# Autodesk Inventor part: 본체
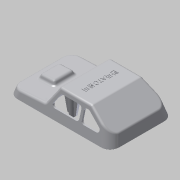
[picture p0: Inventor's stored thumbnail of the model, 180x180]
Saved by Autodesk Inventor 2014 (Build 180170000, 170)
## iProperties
Created: 2015-05
Part Number: 본체
Material: ABS 플라스틱
Document SubType Name: Modeling
Designer: Administrator
Density: 1.06 g/cm^3
Appearance: 매끄러움 - 흰색
Mass: 32.5107 g
Surface Area: 310.046 cm^2
Volume: 30.6705 cm^3
Author: Administrator
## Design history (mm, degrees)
sketch "스케치2"
  geometry: L1 (61, 0)-(-61, 0); L2 (-61, 0)-(-61, 10); L3 (-61, 10)-(-57.782, 12.011); L4 (6.614, 30)-(19.058, 10.086); L5 (19.058, 10.086)-(58.856, 8); L6 (61, 7.888)-(61, 0); L7 (61, 0)-(58.856, 8); L8 (58.856, 8)-(61, 7.888); L9 (-61, 0)-(-57.782, 12.011); L10 (6.614, 30)-(-31, 30); L11 (-31, 30)-(-57.782, 12.011); 2 further points
  constraints: 22 end point, 3 perpendicular, 1 coincident, 1 collinear, 1 horizontal, 1 midpoint, 1 parallel
  dimensions: "d0" = 122 distance of L1.start L1.end; "d1" = 3 deg angle of L1 L5; "d2" = 15 deg angle of L6 L7; "d3" = 8 vertical distance of L1.start L5.end; "d4" = 42 distance of L4.end L6.start; "d5" = 125 deg angle of L5 L4; "d6" = 15 deg angle of L2 L9; "d7" = 30 horizontal distance of L10.end L1.end; "d8" = 20 vertical distance of L10.end L2.end; "d39" = 30 horizontal distance of L2.end L10.end
extrude "돌출1" new body sketch "스케치2" stored distance "d10" = 76; taper "d11" = 0 deg
sketch "스케치3"
  geometry: L1 (-38, 30)-(-38, 10.086) reference; L2 (38, 30)-(-38, 30) reference; L3 (-38, 30)-(-29.962, 30); L4 (-29.962, 30)-(-38, 0); L5 (-38, 0)-(-38, 30); 2 further points
  constraints: 6 end point, 2 collinear, 1 coincident, 1 perpendicular
  dimensions: "d12" = 15 deg angle of L1 L4
extrude "돌출2" cut sketch "스케치3" stored distance "d13" = 76; taper "d14" = 0 deg
fillet "모깎기1" dims "d15" = 12
sketch "스케치4"
  geometry: L1 (-39.853, 59.563)-(-39.853, 11.032) reference; L2 (-31.413, 48.298)-(-11.413, 48.298); L3 (-11.413, 48.298)-(-11.413, 22.298); L4 (-11.413, 22.298)-(-31.413, 22.298); L5 (-31.413, 22.298)-(-31.413, 48.298); L6 (-42.413, 8.889)-(-42.413, 61.706) reference; 3 further points
  constraints: 8 end point, 2 midpoint, 2 parallel, 1 horizontal, 1 horizontal alignment, 1 perpendicular
  dimensions: "d16" = 20 distance of L2.start L2.end; "d17" = 26 distance of L2.end L3.end; "d18" = 11 distance between parallel lines of L6 L5
extrude "돌출3" join sketch "스케치4" distance "d19" = 5; taper "d20" = -20 deg
fillet "모깎기2" dims "d21" = 3
fillet "모깎기3" dims "d22" = 3
feature "쉘1" dims "d23" = 2
sketch "스케치5"
  geometry: L1 (98.679, -73.929)-(0.139, -73.929) reference; L2 (-9.521, -64.27)-(-9.521, -11.73) reference; L3 (0.139, -2.071)-(98.679, -2.071) reference; L4 (108.338, -11.73)-(108.338, -64.27) reference; L5 (98.679, -1.071)-(0.139, -1.071); L6 (-10.521, -11.73)-(-10.521, -64.27); L7 (0.139, -74.929)-(98.679, -74.929); L8 (109.338, -64.27)-(109.338, -11.73); 5 further points; 4 other entities
  constraints: 8 end point, 7 parallel, 16 other
  dimensions: "d24" = 1 distance between parallel lines of L5 L3
extrude "돌출4" join sketch "스케치5" distance "d25" = 1; taper "d26" = 0 deg
node "작업 평면2"
sketch "스케치7"
  geometry: L1 (7.495, 28.59)-(18.23, 11.41) reference; L2 (-30.086, 30)-(4.951, 30) reference; L3 (-46.246, 19.759)-(-31.759, 29.49) reference; L4 (10.347, 14.59)-(4.723, 23.59); L5 (2.179, 25)-(-17.785, 25); L6 (-20.785, 22)-(-20.785, 13); L7 (-17.785, 10)-(7.803, 10); L8 (-23.808, 22)-(-23.808, 13); L9 (-26.808, 10)-(-41.962, 10); L10 (-43.634, 15.49)-(-30.235, 24.49); L11 (-28.563, 25)-(-26.808, 25); A1 r 3 centre (2.179, 22) between (4.723, 23.59) and (2.179, 25); A2 r 3 centre (7.803, 13) between (7.803, 10) and (10.347, 14.59); A3 r 3 centre (-17.785, 13) between (-20.785, 13) and (-17.785, 10); A4 r 3 centre (-17.785, 22) between (-17.785, 25) and (-20.785, 22); A5 r 3 centre (-26.808, 22) between (-23.808, 22) and (-26.808, 25); A6 r 3 centre (-28.563, 22) between (-28.563, 25) and (-30.235, 24.49); A7 r 3 centre (-26.808, 13) between (-26.808, 10) and (-23.808, 13); A8 r 3 centre (-41.962, 13) between (-43.634, 15.49) and (-41.962, 10); 7 further points
  constraints: 16 end point, 16 point on circle, 16 tangent, 12 point on line, 8 centre point, 7 equal radius, 4 parallel, 4 perpendicular
  dimensions: "d41" = 5 distance between parallel lines of L1 L4; "d42" = 5 distance between parallel lines of L2 L5; "d43" = 34 distance of point (-20.785, 10) point (13.215, 10); "d44" = 15 distance of point (-20.785, 25) point (-20.785, 10); "d45" = 15 distance of point (-23.808, 25) point (-23.808, 10); "d46" = 28 distance of point (-23.808, 10) point (-51.808, 10); "d47" = 5 distance between parallel lines of L3 L10; "d48" = 5 distance between parallel lines of L2 L11; "d49" = 3 radius of A1
extrude "돌출5" cut sketch "스케치7" stored distance "d50" = 1; taper "d51" = 0 deg
sketch "스케치8"
  geometry: L1 (65.951, -1.251)-(65.951, -54.068) reference; 2 further points
  constraints: 1 horizontal alignment, 1 other
  dimensions: "d52" = 50 distance from line of L1 point (15.951, -27.66)
feature "엠보싱1" sketch "스케치8" dims "d0" = 122, "d12" = 15 deg, "d53" = 0.5, "d54" = 0
sketch "스케치9"
  geometry: C1 r 3 at (0, -22); C2 r 3 at (0, 22); C3 r 3 at (40, 0); C4 r 3 at (-40, 0); 1 further point
  constraints: 4 centre point, 2 horizontal alignment, 2 vertical alignment
  dimensions: "d55" = 6 diameter of C3; "d56" = 6 diameter of C1; "d57" = 6 diameter of C2; "d58" = 6 diameter of C4; "d59" = 40 distance of C3.centre point (0, 0); "d60" = 40 distance of C4.centre point (0, 0); "d61" = 22 distance of C1.centre point (0, 0); "d62" = 22 distance of point (0, 0) C2.centre
extrude "돌출6" join sketch "스케치9" stored distance "d63" = 1; taper "d64" = 2 deg
node "작업 평면3"
sketch "스케치10"
  geometry: L1 (-45, -1)-(-35, -1); L2 (-35, -1)-(-35, 1); L3 (-35, 1)-(-45, 1); L4 (-45, 1)-(-45, -1); L5 (-45, -1)-(-35, 1); L6 (-35, -1)-(-45, 1); L7 (-5, 21)-(5, 21); L8 (5, 21)-(5, 23); L9 (5, 23)-(-5, 23); L10 (-5, 23)-(-5, 21); L11 (-5, 21)-(5, 23); L12 (5, 21)-(-5, 23); L13 (35, -1)-(45, -1); L14 (45, -1)-(45, 1); L15 (45, 1)-(35, 1); L16 (35, 1)-(35, -1); L17 (35, -1)-(45, 1); L18 (45, -1)-(35, 1); L19 (-5, -23)-(5, -23); L20 (5, -23)-(5, -21); L21 (5, -21)-(-5, -21); L22 (-5, -21)-(-5, -23); L23 (-5, -23)-(5, -21); L24 (5, -23)-(-5, -21); C1 r 3 at (-40, 0) reference; C2 r 3 at (0, -22) reference; C3 r 3 at (0, 22) reference; C4 r 3 at (40, 0) reference; 1 further point
  constraints: 48 end point, 8 midpoint, 8 parallel, 4 horizontal, 4 perpendicular
  dimensions: "d66" = 10 distance of L3.end L2.end; "d67" = 2 distance of L2.end L1.end; "d68" = 10 distance of L9.end L8.end; "d69" = 2 distance of L8.end L7.end; "d70" = 10 distance of L15.end L14.end; "d71" = 2 distance of L14.end L13.end; "d72" = 10 distance of L21.end L20.end; "d73" = 2 distance of L20.end L19.end
  node "투영된 루프1"
  node "투영된 루프2"
  node "투영된 루프3"
  node "투영된 루프4"
extrude "돌출7" join sketch "스케치10" stored distance "d74" = 1; taper "d75" = 2.5 deg
extrude "돌출14" join sketch "스케치10" stored distance "d95" = 1; taper "d96" = 4 deg
sketch "스케치19"
  geometry: L1 (37, 0)-(43, 0) reference; L2 (35, 2)-(34.282, 12.262) reference; L3 (35, 2)-(33.371, 11.24); L4 (33.554, 11.671)-(33.117, 10.641) reference; A1 r 5 centre (28.514, 12.594) between (28.252, 7.601) and (33.117, 10.641) reference; A2 r 1 centre (34.474, 11.281) between (34.527, 12.279) and (33.554, 11.671) reference; 1 further point
  constraints: 2 end point, 1 point on line
  dimensions: "d100" = 80 deg angle of L1 L3
extrude "돌출17" join sketch "스케치19" stored distance "d103" = 1; taper "d104" = 0 deg
sketch "스케치20"
  geometry: L1 (45, 2)-(45.678, 11.695) reference; L2 (47.573, 10.937)-(47.901, 9.866) reference; L3 (34.527, 12.279)-(46.669, 11.643) reference; L4 (45, 2)-(46.959, 11.628); A1 r 5 centre (52.682, 11.328) between (47.901, 9.866) and (52.42, 6.335) reference; A2 r 1 centre (46.617, 10.644) between (47.573, 10.937) and (46.669, 11.643) reference; 1 further point
  constraints: 2 end point, 1 point on line
  dimensions: "d105" = 7.5 deg angle of L1 L4
extrude "돌출18" join sketch "스케치20" stored distance "d106" = 0; taper "d107" = 0 deg
sketch "스케치21"
  geometry: L1 (-35, 2)-(-33.97, 25.596) reference; L2 (-45, 2)-(-45.687, 17.726) reference; L3 (-55.733, 10.978)-(-45.131, 18.099) reference; L4 (4.951, 28)-(-30.086, 28) reference; L5 (-45, 2)-(-47.552, 16.473); 1 further point
  constraints: 2 end point, 1 point on line
  dimensions: "d108" = 7.5 deg angle of L2 L5
extrude "돌출19" join sketch "스케치21" stored distance "d109" = 1; taper "d110" = 0 deg
sketch "스케치22"
  geometry: L1 (-35, 2)-(-33.97, 25.596) reference; L2 (-30.086, 28)-(4.951, 28) reference; L3 (-45.131, 18.099)-(-30.644, 27.83) reference; L4 (-35, 2)-(-30.426, 27.94); A1 r 1 centre (-30.086, 27) between (-30.086, 28) and (-30.644, 27.83) reference; 1 further point
  constraints: 2 end point, 1 point on circle
  dimensions: "d111" = 7.5 deg angle of L1 L4
extrude "돌출20" join sketch "스케치22" stored distance "d112" = 1; taper "d113" = 0 deg
node "작업 평면4"
sketch "스케치23"
  geometry: L1 (5, 2)-(6.094, 27.058) reference; L2 (5.799, 27.53)-(16.534, 10.35) reference; L3 (5, 2)-(8.687, 22.908); 1 further point
  constraints: 2 end point, 1 point on line
  dimensions: "d115" = 7.5 deg angle of L1 L3
extrude "돌출21" join sketch "스케치23" stored distance "d116" = 1; taper "d117" = 0 deg
sketch "스케치24"
  geometry: L1 (-5, 2)-(-6.135, 28) reference; L2 (-30.086, 28)-(4.951, 28) reference; L3 (-5, 2)-(-9.585, 28); 1 further point
  constraints: 2 end point, 1 point on line
  dimensions: "d118" = 7.5 deg angle of L1 L3
extrude "돌출22" join sketch "스케치24" stored distance "d119" = 1; taper "d120" = 0 deg
sketch "스케치25"
  geometry: C1 r 3 at (0, 0) reference; C2 r 3 at (-40, 22) reference; C3 r 3 at (0, 44) reference; C4 r 3 at (40, 22) reference; 5 further points
  constraints: 4 coincident
hole "구멍1" sketch "스케치25" at (0, 44), (40, 22), (0, 0), (-40, 22) diameter "d121" = 3.242; stored, may be unused: countersink angle "d125" = 90 deg, drill point angle "d127" = 118 deg; dims "d122" = 9, "d123" = 4, "d124" = 2, "d126" = 11
node "작업 평면5"
sketch "스케치26"
  geometry: L1 (-26.409, 0)-(26.409, 0) reference; L2 (25, 0)-(17, 0); L3 (14, 0)-(6, 0); A1 r 4 centre (21, 0) between (25, 0) and (17, 0); A2 r 4 centre (10, 0) between (14, 0) and (6, 0); 2 further points
  constraints: 6 horizontal alignment, 4 end point, 4 point on circle, 3 point on line, 2 centre point, 2 collinear, 1 midpoint
  dimensions: "d129" = 4 radius of A1; "d130" = 21 distance of point (0, 0) A1.centre; "d131" = 4 radius of A2; "d132" = 10 distance of point (0, 0) A2.centre
extrude "돌출23" join sketch "스케치26" stored distance "d133" = 1; taper "d134" = 0 deg
chamfer "모따기1" distance "d135" = 1; stored, may be unused: second distance "d136" = 2, angle "d137" = 45 deg
node "솔리드1"
mirror "대칭1"
mirror "대칭2"
mirror "대칭5"
mirror "대칭6"
node "투영된 루프5"
node "투영된 루프6"
node "투영된 루프7"
other parameters: "d40" = -38, "d65" = 2, "d114" = -22, "d128" = -63
